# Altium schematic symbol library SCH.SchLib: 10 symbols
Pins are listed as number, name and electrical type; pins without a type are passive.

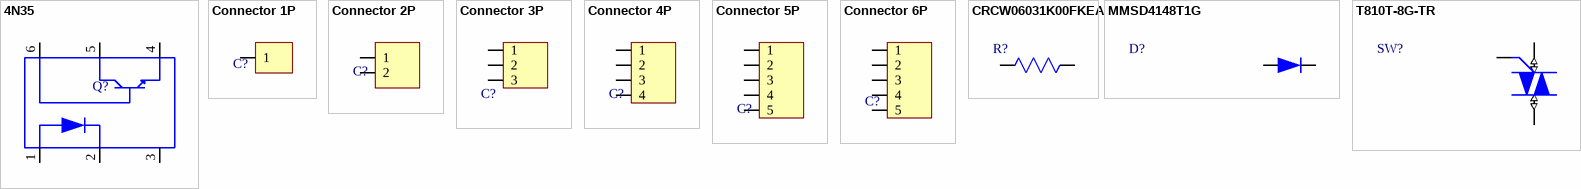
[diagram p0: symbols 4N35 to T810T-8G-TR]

## 4N35
designator Q?  (value not drawn)
Optoisolator Transistor with Base Output 5000Vrms 1 Channel 6-DIP; MF: Vishay; MP: 4N35
footprint DIP6-2.54-7.3X6.5MM
pins: 1 ANODE (io), 2 CATHODE (io), 3 NC (io), 4 EMITER (io), 5 COLLECTOR (io), 6 BASE (io)

## Connector 1P
designator C?  (value not drawn)
pins: 1

## Connector 2P
designator C?  (value not drawn)
pins: 1, 2

## Connector 3P
designator C?  (value not drawn)
pins: 1, 2, 3

## Connector 4P
designator C?  (value not drawn)
pins: 1, 2, 3, 4

## Connector 5P
designator C?  (value not drawn)
pins: 1, 2, 3, 4, 5

## Connector 6P
designator C?  (value not drawn)
pins: 1, 2, 3, 4, 5

## CRCW06031K00FKEA
designator R?  (value not drawn)
D11/CRCW0603 100 1K 1% ET1 e3; Manufacturer_Name: Vishay
footprint RES_CRCW_0603
pins: 1, 2

## MMSD4148T1G
designator D?  (value not drawn)
DIODE; Manufacturer_Name: onsemi
footprint SOD-123_ONS
pins: 1 K, 2 A

## T810T-8G-TR
designator SW?  (value not drawn)
8A 800V 150&#176;C D&#178;PAK Logic Level T-Series Triac; Manufacturer_Name: STMicroelectronics
footprint D2PAK_T2550_STM
pins: 1 A1 (io), 2 A2 (io), 3 G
